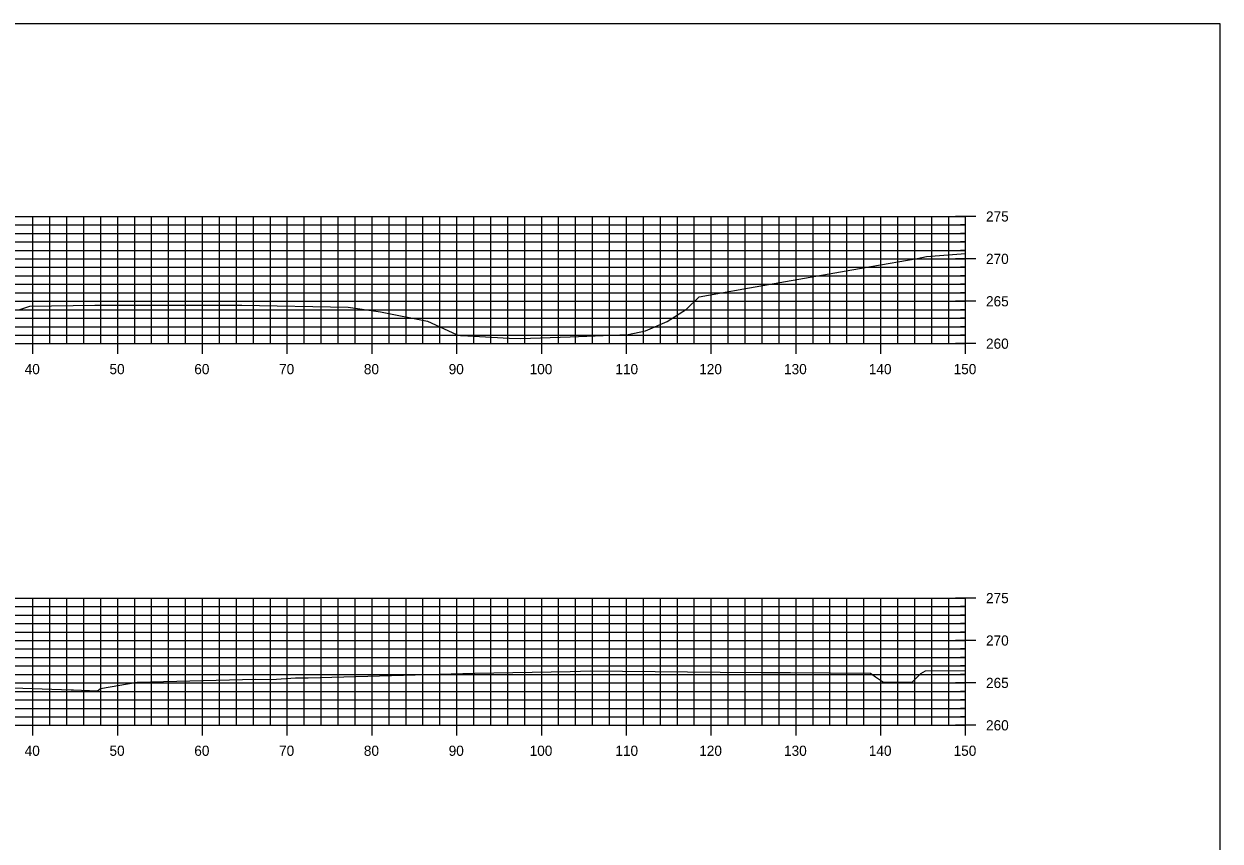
# Model space of a CAD drawing. Extents: x 1661012 to 1662122, y 670053 to 671852.
# Drawn here: x 1661230.9 to 1661372, y 671370.5 to 671466.8 of the extents above; entities that cross this region are included whole.
import ezdxf

# ---------------------------------------------------------------- set-up
doc = ezdxf.new("R2010")
doc.units = 0
for name, color, linetype in [('R_Concrete', 7, 'Continuous'), ('R_Concrete Hidden', 7, 'Continuous'), ('R_Erosion', 7, 'Continuous'), ('R_Exist Surface', 7, 'Continuous'), ('R_Proposed Road', 7, 'Continuous')]:
    doc.layers.add(name, color=color, linetype=linetype)

msp = doc.modelspace()

# ---------------------------------------------------------------- linework, layer by layer
at = {"layer": 'R_Concrete'}
for p, q in [((1661041.99, 671444.12), (1661341.99, 671444.12)), ((1661231.99, 671429.12), (1661231.99, 671444.12)), ((1661233.99, 671429.12), (1661233.99, 671444.12)), ((1661235.99, 671429.12), (1661235.99, 671444.12)), ((1661237.99, 671429.12), (1661237.99, 671444.12)), ((1661239.99, 671429.12), (1661239.99, 671444.12)), ((1661241.99, 671429.12), (1661241.99, 671444.12)), ((1661243.99, 671429.12), (1661243.99, 671444.12)), ((1661245.99, 671429.12), (1661245.99, 671444.12)), ((1661247.99, 671429.12), (1661247.99, 671444.12)), ((1661249.99, 671429.12), (1661249.99, 671444.12)), ((1661251.99, 671429.12), (1661251.99, 671444.12)), ((1661253.99, 671429.12), (1661253.99, 671444.12)), ((1661255.99, 671429.12), (1661255.99, 671444.12)), ((1661257.99, 671429.12), (1661257.99, 671444.12)), ((1661259.99, 671429.12), (1661259.99, 671444.12)), ((1661261.99, 671429.12), (1661261.99, 671444.12)), ((1661263.99, 671429.12), (1661263.99, 671444.12)), ((1661265.99, 671429.12), (1661265.99, 671444.12)), ((1661267.99, 671429.12), (1661267.99, 671444.12)), ((1661269.99, 671429.12), (1661269.99, 671444.12)), ((1661271.99, 671429.12), (1661271.99, 671444.12)), ((1661273.99, 671429.12), (1661273.99, 671444.12)), ((1661275.99, 671429.12), (1661275.99, 671444.12)), ((1661277.99, 671429.12), (1661277.99, 671444.12)), ((1661279.99, 671429.12), (1661279.99, 671444.12)), ((1661281.99, 671429.12), (1661281.99, 671444.12)), ((1661283.99, 671429.12), (1661283.99, 671444.12)), ((1661285.99, 671429.12), (1661285.99, 671444.12)), ((1661287.99, 671429.12), (1661287.99, 671444.12)), ((1661289.99, 671429.12), (1661289.99, 671444.12)), ((1661291.99, 671429.12), (1661291.99, 671444.12)), ((1661293.99, 671429.12), (1661293.99, 671444.12)), ((1661295.99, 671429.12), (1661295.99, 671444.12)), ((1661297.99, 671429.12), (1661297.99, 671444.12)), ((1661299.99, 671429.12), (1661299.99, 671444.12)), ((1661301.99, 671429.12), (1661301.99, 671444.12)), ((1661303.99, 671429.12), (1661303.99, 671444.12)), ((1661305.99, 671429.12), (1661305.99, 671444.12)), ((1661307.99, 671429.12), (1661307.99, 671444.12)), ((1661309.99, 671429.12), (1661309.99, 671444.12)), ((1661311.99, 671429.12), (1661311.99, 671444.12)), ((1661313.99, 671429.12), (1661313.99, 671444.12)), ((1661315.99, 671429.12), (1661315.99, 671444.12)), ((1661317.99, 671429.12), (1661317.99, 671444.12)), ((1661319.99, 671429.12), (1661319.99, 671444.12)), ((1661321.99, 671429.12), (1661321.99, 671444.12)), ((1661323.99, 671429.12), (1661323.99, 671444.12)), ((1661325.99, 671429.12), (1661325.99, 671444.12)), ((1661327.99, 671429.12), (1661327.99, 671444.12)), ((1661329.99, 671429.12), (1661329.99, 671444.12)), ((1661331.99, 671429.12), (1661331.99, 671444.12)), ((1661333.99, 671429.12), (1661333.99, 671444.12)), ((1661335.99, 671429.12), (1661335.99, 671444.12)), ((1661337.99, 671429.12), (1661337.99, 671444.12)), ((1661339.99, 671429.12), (1661339.99, 671444.12)), ((1661343.19, 671444.12), (1661340.79, 671444.12)), ((1661341.99, 671429.12), (1661341.99, 671444.12)), ((1661041.99, 671443.12), (1661341.99, 671443.12)), ((1661341.99, 671443.12), (1661341.39, 671443.12)), ((1661041.99, 671442.12), (1661341.99, 671442.12)), ((1661041.99, 671441.12), (1661341.99, 671441.12)), ((1661341.99, 671442.12), (1661341.39, 671442.12)), ((1661341.99, 671441.12), (1661341.39, 671441.12)), ((1661041.99, 671440.12), (1661341.99, 671440.12)), ((1661341.99, 671440.12), (1661341.39, 671440.12)), ((1661041.99, 671439.12), (1661341.99, 671439.12)), ((1661041.99, 671438.12), (1661341.99, 671438.12)), ((1661343.19, 671439.12), (1661340.79, 671439.12)), ((1661341.99, 671438.12), (1661341.39, 671438.12)), ((1661041.99, 671437.12), (1661341.99, 671437.12)), ((1661341.99, 671437.12), (1661341.39, 671437.12)), ((1661041.99, 671436.12), (1661341.99, 671436.12)), ((1661341.99, 671436.12), (1661341.39, 671436.12)), ((1661041.99, 671435.12), (1661341.99, 671435.12)), ((1661041.99, 671434.12), (1661341.99, 671434.12)), ((1661343.19, 671434.12), (1661340.79, 671434.12)), ((1661341.99, 671435.12), (1661341.39, 671435.12)), ((1661041.99, 671433.12), (1661341.99, 671433.12)), ((1661341.99, 671433.12), (1661341.39, 671433.12)), ((1661041.99, 671432.12), (1661341.99, 671432.12)), ((1661041.99, 671431.12), (1661341.99, 671431.12)), ((1661341.99, 671432.12), (1661341.39, 671432.12)), ((1661341.99, 671431.12), (1661341.39, 671431.12)), ((1661041.99, 671430.12), (1661341.99, 671430.12)), ((1661231.99, 671427.92), (1661231.99, 671430.32)), ((1661233.99, 671429.12), (1661233.99, 671429.72)), ((1661235.99, 671429.12), (1661235.99, 671429.72)), ((1661237.99, 671429.12), (1661237.99, 671429.72)), ((1661239.99, 671429.12), (1661239.99, 671429.72)), ((1661241.99, 671427.92), (1661241.99, 671430.32)), ((1661243.99, 671429.12), (1661243.99, 671429.72)), ((1661245.99, 671429.12), (1661245.99, 671429.72)), ((1661247.99, 671429.12), (1661247.99, 671429.72)), ((1661249.99, 671429.12), (1661249.99, 671429.72)), ((1661251.99, 671427.92), (1661251.99, 671430.32)), ((1661253.99, 671429.12), (1661253.99, 671429.72)), ((1661255.99, 671429.12), (1661255.99, 671429.72)), ((1661257.99, 671429.12), (1661257.99, 671429.72)), ((1661259.99, 671429.12), (1661259.99, 671429.72)), ((1661261.99, 671427.92), (1661261.99, 671430.32)), ((1661263.99, 671429.12), (1661263.99, 671429.72)), ((1661265.99, 671429.12), (1661265.99, 671429.72)), ((1661267.99, 671429.12), (1661267.99, 671429.72)), ((1661269.99, 671429.12), (1661269.99, 671429.72)), ((1661271.99, 671427.92), (1661271.99, 671430.32)), ((1661273.99, 671429.12), (1661273.99, 671429.72)), ((1661275.99, 671429.12), (1661275.99, 671429.72)), ((1661277.99, 671429.12), (1661277.99, 671429.72)), ((1661279.99, 671429.12), (1661279.99, 671429.72)), ((1661281.99, 671427.92), (1661281.99, 671430.32)), ((1661283.99, 671429.12), (1661283.99, 671429.72)), ((1661285.99, 671429.12), (1661285.99, 671429.72)), ((1661287.99, 671429.12), (1661287.99, 671429.72)), ((1661289.99, 671429.12), (1661289.99, 671429.72)), ((1661291.99, 671427.92), (1661291.99, 671430.32)), ((1661293.99, 671429.12), (1661293.99, 671429.72)), ((1661295.99, 671429.12), (1661295.99, 671429.72)), ((1661297.99, 671429.12), (1661297.99, 671429.72)), ((1661299.99, 671429.12), (1661299.99, 671429.72)), ((1661301.99, 671427.92), (1661301.99, 671430.32)), ((1661303.99, 671429.12), (1661303.99, 671429.72)), ((1661305.99, 671429.12), (1661305.99, 671429.72)), ((1661307.99, 671429.12), (1661307.99, 671429.72)), ((1661309.99, 671429.12), (1661309.99, 671429.72)), ((1661311.99, 671427.92), (1661311.99, 671430.32)), ((1661313.99, 671429.12), (1661313.99, 671429.72)), ((1661315.99, 671429.12), (1661315.99, 671429.72)), ((1661317.99, 671429.12), (1661317.99, 671429.72)), ((1661319.99, 671429.12), (1661319.99, 671429.72)), ((1661321.99, 671427.92), (1661321.99, 671430.32)), ((1661323.99, 671429.12), (1661323.99, 671429.72)), ((1661325.99, 671429.12), (1661325.99, 671429.72)), ((1661327.99, 671429.12), (1661327.99, 671429.72)), ((1661329.99, 671429.12), (1661329.99, 671429.72)), ((1661331.99, 671427.92), (1661331.99, 671430.32)), ((1661333.99, 671429.12), (1661333.99, 671429.72)), ((1661335.99, 671429.12), (1661335.99, 671429.72)), ((1661337.99, 671429.12), (1661337.99, 671429.72)), ((1661339.99, 671429.12), (1661339.99, 671429.72)), ((1661341.99, 671430.12), (1661341.39, 671430.12)), ((1661341.99, 671427.92), (1661341.99, 671430.32)), ((1661041.99, 671429.12), (1661341.99, 671429.12)), ((1661343.19, 671429.12), (1661340.79, 671429.12)), ((1661041.99, 671399.12), (1661341.99, 671399.12)), ((1661231.99, 671384.12), (1661231.99, 671399.12)), ((1661233.99, 671384.12), (1661233.99, 671399.12)), ((1661235.99, 671384.12), (1661235.99, 671399.12)), ((1661237.99, 671384.12), (1661237.99, 671399.12)), ((1661239.99, 671384.12), (1661239.99, 671399.12)), ((1661241.99, 671384.12), (1661241.99, 671399.12)), ((1661243.99, 671384.12), (1661243.99, 671399.12)), ((1661245.99, 671384.12), (1661245.99, 671399.12)), ((1661247.99, 671384.12), (1661247.99, 671399.12)), ((1661249.99, 671384.12), (1661249.99, 671399.12)), ((1661251.99, 671384.12), (1661251.99, 671399.12)), ((1661253.99, 671384.12), (1661253.99, 671399.12)), ((1661255.99, 671384.12), (1661255.99, 671399.12)), ((1661257.99, 671384.12), (1661257.99, 671399.12)), ((1661259.99, 671384.12), (1661259.99, 671399.12)), ((1661261.99, 671384.12), (1661261.99, 671399.12)), ((1661263.99, 671384.12), (1661263.99, 671399.12)), ((1661265.99, 671384.12), (1661265.99, 671399.12)), ((1661267.99, 671384.12), (1661267.99, 671399.12)), ((1661269.99, 671384.12), (1661269.99, 671399.12)), ((1661271.99, 671384.12), (1661271.99, 671399.12)), ((1661273.99, 671384.12), (1661273.99, 671399.12)), ((1661275.99, 671384.12), (1661275.99, 671399.12)), ((1661277.99, 671384.12), (1661277.99, 671399.12)), ((1661279.99, 671384.12), (1661279.99, 671399.12)), ((1661281.99, 671384.12), (1661281.99, 671399.12)), ((1661283.99, 671384.12), (1661283.99, 671399.12)), ((1661285.99, 671384.12), (1661285.99, 671399.12)), ((1661287.99, 671384.12), (1661287.99, 671399.12)), ((1661289.99, 671384.12), (1661289.99, 671399.12)), ((1661291.99, 671384.12), (1661291.99, 671399.12)), ((1661293.99, 671384.12), (1661293.99, 671399.12)), ((1661295.99, 671384.12), (1661295.99, 671399.12)), ((1661297.99, 671384.12), (1661297.99, 671399.12)), ((1661299.99, 671384.12), (1661299.99, 671399.12)), ((1661301.99, 671384.12), (1661301.99, 671399.12)), ((1661303.99, 671384.12), (1661303.99, 671399.12)), ((1661305.99, 671384.12), (1661305.99, 671399.12)), ((1661307.99, 671384.12), (1661307.99, 671399.12)), ((1661309.99, 671384.12), (1661309.99, 671399.12)), ((1661311.99, 671384.12), (1661311.99, 671399.12)), ((1661313.99, 671384.12), (1661313.99, 671399.12)), ((1661315.99, 671384.12), (1661315.99, 671399.12)), ((1661317.99, 671384.12), (1661317.99, 671399.12)), ((1661319.99, 671384.12), (1661319.99, 671399.12)), ((1661321.99, 671384.12), (1661321.99, 671399.12)), ((1661323.99, 671384.12), (1661323.99, 671399.12)), ((1661325.99, 671384.12), (1661325.99, 671399.12)), ((1661327.99, 671384.12), (1661327.99, 671399.12)), ((1661329.99, 671384.12), (1661329.99, 671399.12)), ((1661331.99, 671384.12), (1661331.99, 671399.12)), ((1661333.99, 671384.12), (1661333.99, 671399.12)), ((1661335.99, 671384.12), (1661335.99, 671399.12)), ((1661337.99, 671384.12), (1661337.99, 671399.12)), ((1661339.99, 671384.12), (1661339.99, 671399.12)), ((1661343.19, 671399.12), (1661340.79, 671399.12)), ((1661341.99, 671384.12), (1661341.99, 671399.12)), ((1661041.99, 671398.12), (1661341.99, 671398.12)), ((1661041.99, 671397.12), (1661341.99, 671397.12)), ((1661341.99, 671398.12), (1661341.39, 671398.12)), ((1661341.99, 671397.12), (1661341.39, 671397.12)), ((1661041.99, 671396.12), (1661341.99, 671396.12)), ((1661341.99, 671396.12), (1661341.39, 671396.12)), ((1661041.99, 671395.12), (1661341.99, 671395.12)), ((1661341.99, 671395.12), (1661341.39, 671395.12)), ((1661041.99, 671394.12), (1661341.99, 671394.12)), ((1661041.99, 671393.12), (1661341.99, 671393.12)), ((1661343.19, 671394.12), (1661340.79, 671394.12)), ((1661341.99, 671393.12), (1661341.39, 671393.12)), ((1661041.99, 671392.12), (1661341.99, 671392.12)), ((1661341.99, 671392.12), (1661341.39, 671392.12)), ((1661041.99, 671391.12), (1661341.99, 671391.12)), ((1661041.99, 671390.12), (1661341.99, 671390.12)), ((1661341.99, 671391.12), (1661341.39, 671391.12)), ((1661341.99, 671390.12), (1661341.39, 671390.12)), ((1661041.99, 671389.12), (1661341.99, 671389.12)), ((1661343.19, 671389.12), (1661340.79, 671389.12)), ((1661041.99, 671388.12), (1661341.99, 671388.12)), ((1661341.99, 671388.12), (1661341.39, 671388.12)), ((1661041.99, 671387.12), (1661341.99, 671387.12)), ((1661041.99, 671386.12), (1661341.99, 671386.12)), ((1661341.99, 671387.12), (1661341.39, 671387.12)), ((1661341.99, 671386.12), (1661341.39, 671386.12)), ((1661041.99, 671385.12), (1661341.99, 671385.12)), ((1661231.99, 671382.92), (1661231.99, 671385.32)), ((1661233.99, 671384.12), (1661233.99, 671384.72)), ((1661235.99, 671384.12), (1661235.99, 671384.72)), ((1661237.99, 671384.12), (1661237.99, 671384.72)), ((1661239.99, 671384.12), (1661239.99, 671384.72)), ((1661241.99, 671382.92), (1661241.99, 671385.32)), ((1661243.99, 671384.12), (1661243.99, 671384.72)), ((1661245.99, 671384.12), (1661245.99, 671384.72)), ((1661247.99, 671384.12), (1661247.99, 671384.72)), ((1661249.99, 671384.12), (1661249.99, 671384.72)), ((1661251.99, 671382.92), (1661251.99, 671385.32)), ((1661253.99, 671384.12), (1661253.99, 671384.72)), ((1661255.99, 671384.12), (1661255.99, 671384.72)), ((1661257.99, 671384.12), (1661257.99, 671384.72)), ((1661259.99, 671384.12), (1661259.99, 671384.72)), ((1661261.99, 671382.92), (1661261.99, 671385.32)), ((1661263.99, 671384.12), (1661263.99, 671384.72)), ((1661265.99, 671384.12), (1661265.99, 671384.72)), ((1661267.99, 671384.12), (1661267.99, 671384.72)), ((1661269.99, 671384.12), (1661269.99, 671384.72)), ((1661271.99, 671382.92), (1661271.99, 671385.32)), ((1661273.99, 671384.12), (1661273.99, 671384.72)), ((1661275.99, 671384.12), (1661275.99, 671384.72)), ((1661277.99, 671384.12), (1661277.99, 671384.72)), ((1661279.99, 671384.12), (1661279.99, 671384.72)), ((1661281.99, 671382.92), (1661281.99, 671385.32)), ((1661283.99, 671384.12), (1661283.99, 671384.72)), ((1661285.99, 671384.12), (1661285.99, 671384.72)), ((1661287.99, 671384.12), (1661287.99, 671384.72)), ((1661289.99, 671384.12), (1661289.99, 671384.72)), ((1661291.99, 671382.92), (1661291.99, 671385.32)), ((1661293.99, 671384.12), (1661293.99, 671384.72)), ((1661295.99, 671384.12), (1661295.99, 671384.72)), ((1661297.99, 671384.12), (1661297.99, 671384.72)), ((1661299.99, 671384.12), (1661299.99, 671384.72)), ((1661301.99, 671382.92), (1661301.99, 671385.32)), ((1661303.99, 671384.12), (1661303.99, 671384.72)), ((1661305.99, 671384.12), (1661305.99, 671384.72)), ((1661307.99, 671384.12), (1661307.99, 671384.72)), ((1661309.99, 671384.12), (1661309.99, 671384.72)), ((1661311.99, 671382.92), (1661311.99, 671385.32)), ((1661313.99, 671384.12), (1661313.99, 671384.72)), ((1661315.99, 671384.12), (1661315.99, 671384.72)), ((1661317.99, 671384.12), (1661317.99, 671384.72)), ((1661319.99, 671384.12), (1661319.99, 671384.72)), ((1661321.99, 671382.92), (1661321.99, 671385.32)), ((1661323.99, 671384.12), (1661323.99, 671384.72)), ((1661325.99, 671384.12), (1661325.99, 671384.72)), ((1661327.99, 671384.12), (1661327.99, 671384.72)), ((1661329.99, 671384.12), (1661329.99, 671384.72)), ((1661331.99, 671382.92), (1661331.99, 671385.32)), ((1661333.99, 671384.12), (1661333.99, 671384.72)), ((1661335.99, 671384.12), (1661335.99, 671384.72)), ((1661337.99, 671384.12), (1661337.99, 671384.72)), ((1661339.99, 671384.12), (1661339.99, 671384.72)), ((1661341.99, 671385.12), (1661341.39, 671385.12)), ((1661341.99, 671382.92), (1661341.99, 671385.32)), ((1661041.99, 671384.12), (1661341.99, 671384.12)), ((1661343.19, 671384.12), (1661340.79, 671384.12))]:
    msp.add_line(p, q, dxfattribs=at)
at = {"layer": 'R_Erosion'}
for points in [[(1661230.45, 671433.14), (1661231.62, 671433.55), (1661239.29, 671433.67), (1661256.63, 671433.67), (1661269.16, 671433.44), (1661272.97, 671432.88), (1661278.52, 671431.77), (1661281.94, 671430.21), (1661282.16, 671430.11), (1661282.42, 671430.09), (1661283.29, 671430.05), (1661288.15, 671429.78), (1661289.51, 671429.73), (1661295.33, 671429.91), (1661302.17, 671430.19), (1661304.22, 671430.64), (1661306.8, 671431.75), (1661309.08, 671433.17), (1661310.55, 671434.66), (1661315.82, 671435.59), (1661330.8, 671438.2), (1661336.29, 671439.16), (1661337.37, 671439.38), (1661341.99, 671439.77), (1661341.99, 671439.77)], [(1661227.35, 671388.61), (1661236.52, 671388.3), (1661236.77, 671388.3), (1661239.6, 671388.2), (1661239.96, 671388.45), (1661244.29, 671389.19), (1661258.29, 671389.57), (1661260.18, 671389.54), (1661262.95, 671389.7), (1661264.45, 671389.73), (1661284.12, 671390.26), (1661295.36, 671390.48), (1661297.79, 671390.53), (1661301.52, 671390.51), (1661313.04, 671390.37), (1661318.07, 671390.36), (1661321.32, 671390.34), (1661330.75, 671390.26), (1661331.34, 671389.82), (1661332.29, 671389.21), (1661334.95, 671389.22), (1661335.72, 671389.23), (1661336.69, 671390.23), (1661336.71, 671390.23), (1661337.27, 671390.53), (1661341.99, 671390.57)]]:
    msp.add_lwpolyline(points, dxfattribs=at)
at = {"layer": 'R_Exist Surface'}
for p, q in [((1661341.99, 671429.12), (1661341.99, 671444.12)), ((1661041.99, 671429.12), (1661341.99, 671429.12)), ((1661341.99, 671384.12), (1661341.99, 671399.12)), ((1661041.99, 671384.12), (1661341.99, 671384.12))]:
    msp.add_line(p, q, dxfattribs=at)
at = {"layer": 'R_Proposed Road'}
msp.add_lwpolyline([(1661011.99, 671274.12), (1661371.99, 671274.12), (1661371.99, 671466.82), (1661011.99, 671466.82)], close=True, dxfattribs=at)

# ---------------------------------------------------------------- texts
at = {"layer": 'R_Concrete Hidden'}
for s, p in [('275', (1661344.39, 671443.52)), ('270', (1661344.39, 671438.52)), ('265', (1661344.39, 671433.52)), ('260', (1661344.39, 671428.52)), ('40', (1661231.02, 671425.52)), ('50', (1661241.02, 671425.52)), ('60', (1661251.02, 671425.52)), ('70', (1661261.02, 671425.52)), ('80', (1661271.02, 671425.52)), ('90', (1661281.02, 671425.52)), ('100', (1661290.57, 671425.52)), ('110', (1661300.68, 671425.52)), ('120', (1661310.57, 671425.52)), ('130', (1661320.57, 671425.52)), ('140', (1661330.57, 671425.52)), ('150', (1661340.57, 671425.52)), ('275', (1661344.39, 671398.52)), ('270', (1661344.39, 671393.52)), ('265', (1661344.39, 671388.52)), ('260', (1661344.39, 671383.52)), ('40', (1661231.02, 671380.52)), ('50', (1661241.02, 671380.52)), ('60', (1661251.02, 671380.52)), ('70', (1661261.02, 671380.52)), ('80', (1661271.02, 671380.52)), ('90', (1661281.02, 671380.52)), ('100', (1661290.57, 671380.52)), ('110', (1661300.68, 671380.52)), ('120', (1661310.57, 671380.52)), ('130', (1661320.57, 671380.52)), ('140', (1661330.57, 671380.52)), ('150', (1661340.57, 671380.52))]:
    msp.add_text(s, height=1.2, dxfattribs=at).set_placement(p)

doc.saveas('drawing.dxf')
